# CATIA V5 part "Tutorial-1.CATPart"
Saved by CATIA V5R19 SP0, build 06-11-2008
Part number: c11tut1
Bounding box of the stored display mesh (mm): x -74.368 to 0, y -50 to 50, z -100 to 0
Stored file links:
  D:\Shriniwas\v5_r19\Part files\c11\c11tut1.CATPart
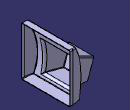
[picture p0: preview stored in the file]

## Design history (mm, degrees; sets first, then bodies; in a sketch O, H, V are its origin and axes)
Body1 (main body)
  Sketch1 on zx-plane, origin (0, 0, 0), H (-1, 0, 0), V (0, 0, 1)
    line L1 (0, 0) -> (12, 0)
    line L2 (0, -100) -> (22, -100)
    point P2 (0, -100)
    arc A1 centre (-96.8872, -61.3887) radius 125 from (12, 0) to (22, -100) cw
    length L1 = 12
    length L2 = 22
    radius A1 = 125
    distance L2 L1 = 100
    horizontal: L1 H, L2 H
    coincidence: P2 V
  Extrude1: Lim1 50, Lim2 50, Element1 Sketch1, Direction zx-plane
  Sketch2 on zx-plane, origin (0, 0, 0), H (-1, 0, 0), V (0, 0, 1)
    line L1 (20, -40) -> (74.9495, -60)
    point P1 (20, -40)
    point P2 (74.9495, -60)
    reference projected line E1 (22, -100) -> (0, -100) from edge of Extrude1
    angle L1 H = 20
    distance P1 V = 20
    distance E1 P1 = 60
    distance H P2 = 60
  Plane1: type Normal, Curve Sketch2, RefPoint Sketch2.P2
  Sketch3 on Plane1, origin (-85.4657, 0, -31.107), H (0, -1, 0), V (-0.342, 0, 0.9397)
    line L1 (-25, -30.7473) -> (25, -30.7473)
    line L2 (25, -30.7473) -> (25, -70.7473)
    line L3 (25, -70.7473) -> (-25, -70.7473)
    line L4 (-25, -70.7473) -> (-25, -30.7473)
    reference projected point E1 (0, -30.7473) from Sketch2.P2
    reference projected point E2 (0, -30.7473) from Sketch2.P2
    length L2 = 40
    length L3 = 50
    distance L4 E2 = 25
    horizontal: L1 H, L3 H
    vertical: L2 V, L4 V
    coincidence: E1 L1
  Plane2: type Normal, Curve Sketch2, RefPoint Sketch2.P1
  Sketch4 on Plane2, origin (-30.5162, 0, -11.107), H (0, -1, 0), V (-0.342, 0, 0.9397)
    line L1 (-32.5, -21.2473) -> (32.5, -21.2473)
    line L2 (32.5, -21.2473) -> (32.5, -81.2473)
    line L3 (32.5, -81.2473) -> (-32.5, -81.2473)
    line L4 (-32.5, -81.2473) -> (-32.5, -21.2473)
    reference projected line E1 (25, -30.7473) -> (-25, -30.7473) from Sketch3.L1
    distance E1 L1 = 9.5
    length L2 = 60
    distance L4 L2 = 65
    distance V L2 = 32.5
    horizontal: L1 H, L3 H
    vertical: L2 V, L4 V
  Loft1: Sections (Sketch4; Sketch3)
  Sketch5 on face of Extrude1 from Sketch1.L1, origin (0, 0, 0), H (1, 0, 0), V (0, -1, 0)
    line L1 (-5, -50) -> (0, -50)
    point P2 (0, -50)
    arc A1 centre (-5, 0) radius 50 from (-29.6886, -43.4796) to (-5, -50) ccw
    reference projected line E1 (0, -50) -> (0, 50) from edge of Extrude1
    reference projected line E2 (-22, -50) -> (0, -50) from edge of Extrude1
    length L1 = 5
    radius A1 = 50
    horizontal: L1 H
    tangency: A1 L1
    coincidence: P2 E1, L1 E2
  Extrude2: Lim1 100, Lim2 0, Element1 Sketch5
  Symmetry1: Reference zx-plane, ToTransfor Extrude2
  Trim1: Trimmed (Extrude2; Extrude1)
  Trim2: Trimmed (Symmetry1; Trim1)
  Trim3: Trimmed (Trim2; Loft1)
  CloseSurface1: CloseElement Trim3
  Sketch6 on face of CloseSurface1, origin (-85.4657, 0, -31.107), H (0, -1, 0), V (-0.342, 0, 0.9397)
    line L1 (-20, -55.7473) -> (0, -55.7473)
    line L2 (0, -55.7473) -> (0, -65.7473)
    line L3 (0, -65.7473) -> (-20, -65.7473)
    line L4 (-20, -65.7473) -> (-20, -55.7473)
    reference projected line E1 (-25, -70.7473) -> (25, -70.7473) from edge [face of CloseSurface1 | face of CloseSurface1]
    reference projected line E2 (-25, -30.7473) -> (-25, -70.7473) from edge [face of CloseSurface1 | face of CloseSurface1]
    length L1 = 20
    length L4 = 10
    distance E1 L3 = 5
    distance L4 E2 = 5
    horizontal: L1 H, L3 H
    vertical: L2 V, L4 V
  Pocket1: profile Sketch6, direction (0.9397, 0, 0.342), length 5
  Fillet1: radius 1, on end face of Pocket1; edge [face of Pocket1 from Sketch6.L1 | face of Pocket1 from Sketch6.L2]; edge [face of Pocket1 from Sketch6.L4 | face of Pocket1 from Sketch6.L1]; edge [face of Pocket1 from Sketch6.L2 | face of Pocket1 from Sketch6.L3]; edge [face of Pocket1 from Sketch6.L3 | face of Pocket1 from Sketch6.L4]
  Fillet2: radius 3.5, on edge [face of CloseSurface1 | face of CloseSurface1] (x4)
  Fillet3: radius 2, on face of CloseSurface1; edge [face of CloseSurface1 | face of CloseSurface1] (x4)
  Shell1: ExtOffset 0, IntOffset 1, Face face of CloseSurface1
